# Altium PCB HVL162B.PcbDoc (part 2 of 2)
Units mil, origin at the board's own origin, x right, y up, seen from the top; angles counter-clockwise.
Board outline 4000 x 2700 mil, 2 copper layers (Top Layer, Bottom Layer), stack 62 mil thick; 115 components, 45 nets, 233 pads, 126 vias.
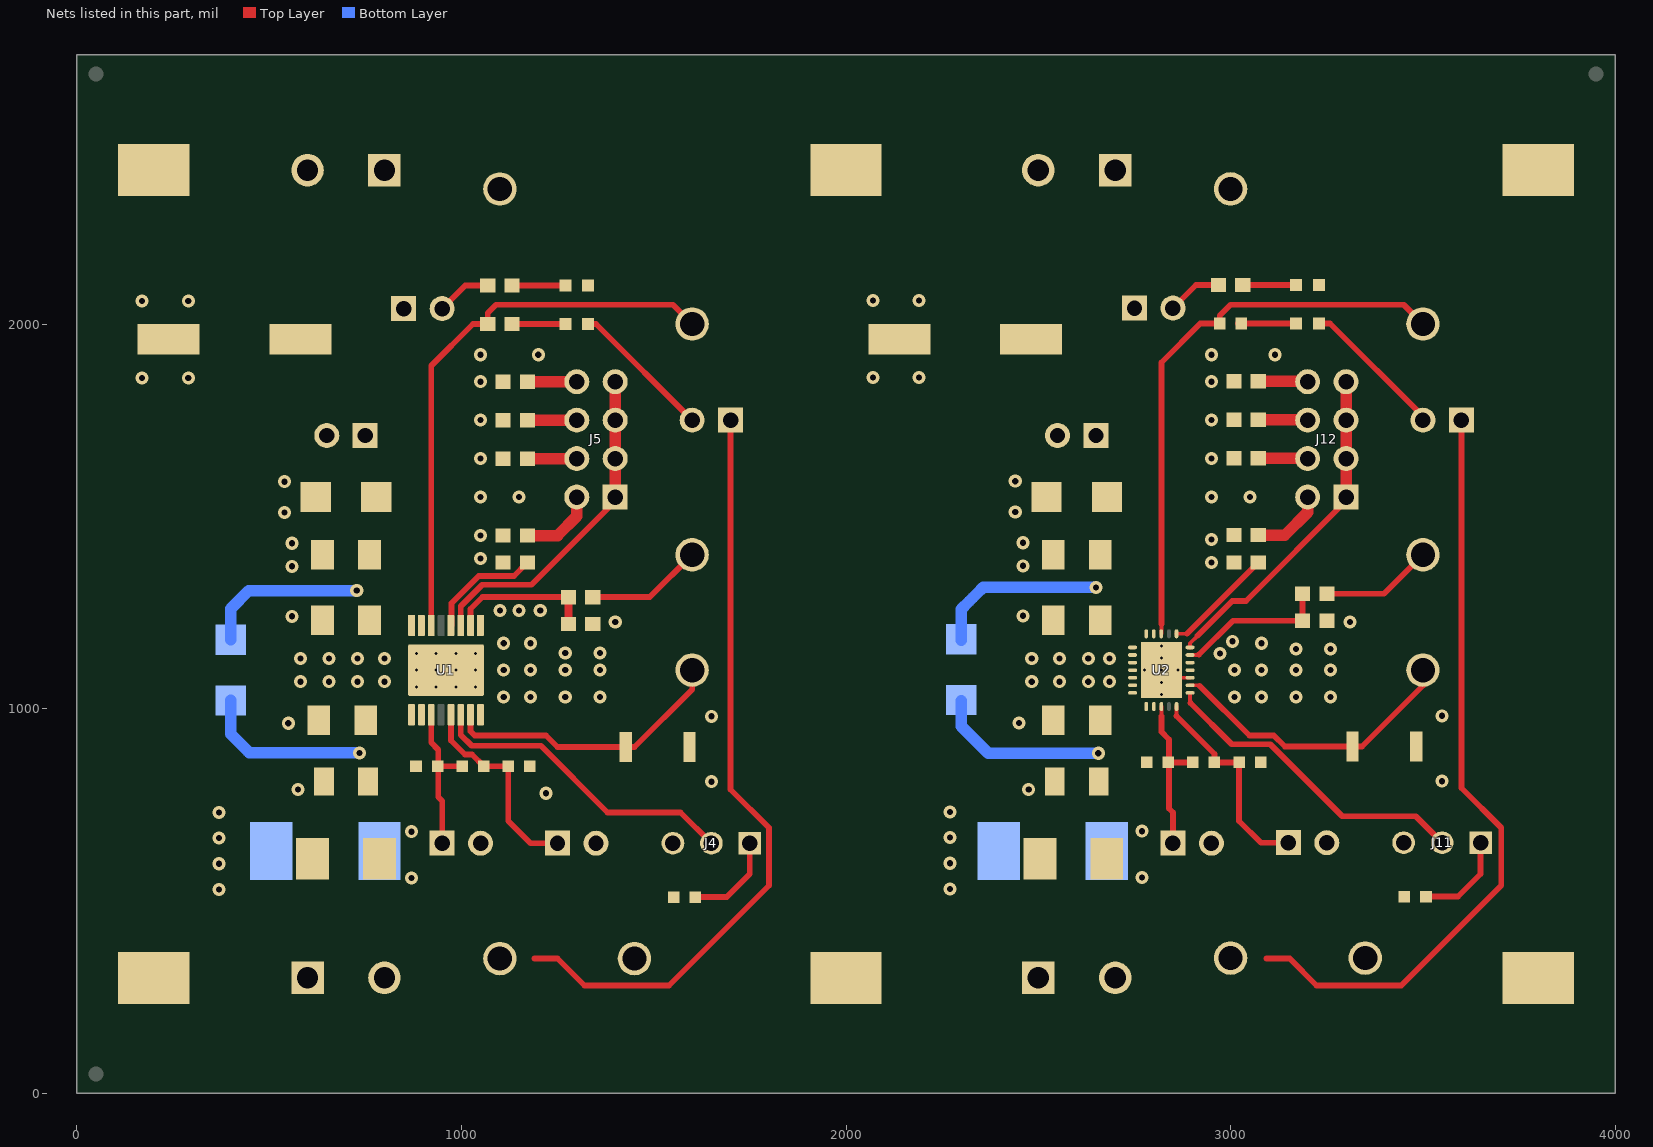
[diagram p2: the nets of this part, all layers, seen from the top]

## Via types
v1: diameter 34, hole 16, Top Layer to Bottom Layer, 107 vias
v2: diameter 19.68, hole 7.87, Top Layer to Bottom Layer, 13 vias
v3: diameter 19.68, hole 7.87, Top Layer to Bottom Layer, tented both sides, 6 vias

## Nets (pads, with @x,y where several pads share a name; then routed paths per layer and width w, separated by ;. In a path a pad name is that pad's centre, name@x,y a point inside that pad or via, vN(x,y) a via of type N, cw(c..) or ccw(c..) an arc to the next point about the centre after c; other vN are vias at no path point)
GND: C1.2 C2.1 C3.2 C4.2 C5.2 C7.2 C8.1 C9.2 C10.2 C11.2 D3.1 D4.1 D5.2 D6.2 D9.1 D10.1 D11.2 D12.2 S1.1 S2.1 T1.1 T2.2 T3.1 T4.2 TP7.1 TP8.1 TP9.1 TP16.1 TP17.1 TP18.1 U1.9 U2.17
  other v1: 370,530 2270,531.3 370,596.67 2270,597.97 370,663.33 2270,664.63 370,730 2270,731.3 575,790 2475,790 1650,810 3550,811.3 550,962 2450,963 1650,980 3550,981.3 2972,1143 3005,1175 560,1240 2460,1241.3 1100,1255 1150,1255 1205,1255 560,1370 2460,1371.3 560,1430 2460,1431.3 540,1510 2440,1511.3 540,1590 2440,1591.3 170,1860 290,1860 2070,1861.3 2190,1861.3 170,2060 290,2060 2070,2061.3 2190,2061.3
NetC5_1: C5.1 J3.2
NetC6_1: C6.1 U1.12 | length 300.6
  Top Layer w15: U1.12@972.8,1216.14 974.15,1216.14 974.15,1274.15 1045,1345 1136.5,1345 C6.1@1171.5,1380
NetC9_1: C9.1 J10.2
NetC12_1: C12.1 U2.20 | length 289.3
  Top Layer w10: U2.20@2859.37,1194.49 2886.32,1194.49
  Top Layer w15: 2886.32,1194.49 C12.1@3071.83,1380
NetD1_1: D1.1 J1.2 | length 374
  Top Layer w15: D1.1@1329.53,2000 1350,2000 J1.2@1600,1750
NetD1_2: D1.2 R1.2 | length 139
  Top Layer w15: R1.2@1131.5,2000 D1.2@1270.47,2000
NetD6_1: D6.1 R5.1 | length 139
  Top Layer w15: R5.1@1131.5,2100 D6.1@1270.47,2100
NetD7_1: D7.1 J8.2 | length 380.4
  Top Layer w15: D7.1@3229.53,2001.3 3258.7,2001.3 3500,1760 J8.2@3500,1750
NetD7_2: D7.2 R13.2 | length 151.8
  Top Layer w15: R13.2@3018.7,2001.3 R13.2@3028,2001.3 D7.2@3170.47,2001.3
NetD12_1: D12.1 R16.1 | length 139
  Top Layer w15: R16.1@3031.5,2101.3 D12.1@3170.47,2101.3
NetJ2_2: J2.2 R5.2 | length 143.4
  Top Layer w15: J2.2@950,2040 1010,2100 R5.2@1068.5,2100
NetJ4_1: J4.1 R7.2 | length 246.9
  Top Layer w15: R7.2@1608,510 1690,510 1750,570 J4.1@1750,650
NetJ4_2: J4.2 U1.6 | length 820.5
  Top Layer w15: U1.6@998.39,983.86 998.39,931.61 1026.75,903.25 1206.75,903.25 1380,730 1570,730 J4.2@1650,650
NetJ5_1: J5.1 J5.3 J5.5 J5.7 U1.11 | length 875
  Top Layer w15: U1.11@998.39,1216.14 998.39,1266.04 1054.47,1322.13 1182.13,1322.13 1400,1540 J5.1@1400,1550
  Top Layer w30: J5.1@1400,1550 J5.3@1400,1650 J5.5@1400,1750 J5.7@1400,1850
NetJ5_2: J5.2 R9.2 | length 199.2
  Top Layer w30: R9.2@1171.5,1450 1250,1450 1300,1500 J5.2@1300,1550
NetJ5_4: J5.4 R10.2 | length 128.5
  Top Layer w30: R10.2@1171.5,1650 J5.4@1300,1650
NetJ5_6: J5.6 R11.2 | length 128.5
  Top Layer w30: R11.2@1171.5,1750 J5.6@1300,1750
NetJ5_8: J5.8 R12.2 | length 128.5
  Top Layer w30: R12.2@1171.5,1850 J5.8@1300,1850
NetJ6_1: J6.1 R2.1 R3.2 U1.3 | length 411.3
  Top Layer w15: U1.3@921.61,983.86 921.61,911.61 940,893.23 940,852 R2.1@938,850 ; J6.1@950,650 950,760 940,770 940,848 R2.1@938,850 ; R3.2@1002,850 R2.1@938,850
NetJ7_1: J7.1 R3.1 R8.2 U1.5 | length 537.7
  Top Layer w15: U1.5@972.8,983.86 972.8,917.2 1009.63,880.37 1027.63,880.37 R3.1@1058,850 R8.2@1122,850 1122,708 1180,650 J7.1@1250,650
NetJ9_2: J9.2 R16.2 | length 143.4
  Top Layer w15: J9.2@2850,2041.3 2910,2101.3 R16.2@2968.5,2101.3
NetJ11_1: J11.1 R19.2 | length 247.6
  Top Layer w15: R19.2@3508,511.3 3591.3,511.3 3650,570 J11.1@3650,651.3
NetJ11_2: J11.2 U2.13 | length 831.7
  Top Layer w10: U2.13@2894.8,1040.94 2894.8,1015.2 2895.75,1014.25
  Top Layer w15: 2895.75,1014.25 3002.87,907.13 3102.87,907.13 3290,720 3481.3,720 J11.2@3550,651.3
NetJ12_1: J12.1 J12.3 J12.5 J12.7 U2.19 | length 879.9
  Top Layer w10: U2.19@2894.8,1159.06 2894.8,1169.8 2913.83,1188.83 2913.83,1189.65
  Top Layer w15: 2913.83,1189.65 3004.18,1280 3040,1280 3300.33,1540.33 J12.1@3300.33,1550
  Top Layer w30: J12.1@3300.33,1550 J12.3@3300.33,1650 J12.5@3300.33,1750 J12.7@3300.33,1850
NetJ12_2: J12.2 R21.2 | length 192.6
  Top Layer w30: R21.2@3071.83,1451.3 3141.3,1451.3 3200.33,1510.33 J12.2@3200.33,1550
NetJ12_4: J12.4 R22.2 | length 127.2
  Top Layer w30: R22.2@3071.83,1651.3 J12.4@3199.03,1651.3
NetJ12_6: J12.6 R23.2 | length 127.2
  Top Layer w30: R23.2@3071.83,1751.3 J12.6@3199.03,1751.3
NetJ12_8: J12.8 R24.2 | length 129
  Top Layer w30: R24.2@3071.83,1851.3 3199.03,1851.3 J12.8@3200.33,1850
NetJ13_1: J13.1 R14.1 R15.2 U2.10 | length 431.9
  Top Layer w10: 2820,980 U2.10@2820,1005.51
  Top Layer w15: 2820,980 2820,940 2840,920 R14.1@2840,860 ; R14.1@2838,860 R14.1@2840,860 ; J13.1@2850,650 2850,730 2840,740 R14.1@2840,860 ; R15.2@2902,860 R14.1@2840,860
NetJ14_1: J14.1 R15.1 R20.2 U2.12 | length 553.9
  Top Layer w10: 2859.37,980.63 U2.12@2859.37,1005.51
  Top Layer w15: 2859.37,980.63 2958,882 R15.1@2958,860 R20.2@3022,860 3022,708 3078.7,651.3 J14.1@3150,651.3
NetR1_1: R1.1 TP1.1 U1.14 | length 1456.9
  Top Layer w15: U1.14@921.61,1216.14 921.61,1891.61 1030,2000 R1.1@1068.5,2000 1068.5,2028.5 1090,2050 1550,2050 TP1.1@1600,2000
NetR4_1: R4.1 TP5.1 | length 304.1
  Top Layer w15: R4.1@1341.5,1290 1490,1290 TP5.1@1600,1400
NetR4_2: R4.2 R6.2 U1.10 | length 380.7
  Top Layer w15: U1.10@1023.98,1216.14 1023.98,1259.28 1055.07,1290.37 1231.37,1290.37 1231.74,1290 R4.2@1278.5,1290
  Top Layer w20: R6.2@1278.5,1220 R4.2@1278.5,1290
NetR13_1: R13.1 TP10.1 U2.22 | length 1480.5
  Top Layer w10: U2.22@2820,1194.49 2820,1220
  Top Layer w15: 2820,1220 2820,1900 2921.3,2001.3 R13.1@2972,2001.3 2972,2022 3000,2050 3450,2050 TP10.1@3500,2000
NetR17_1: R17.1 TP14.1 | length 291.8
  Top Layer w15: R17.1@3250.2,1298.7 3398.7,1298.7 TP14.1@3500,1400
NetR17_2: R17.2 R18.2 U2.18 | length 400.2
  Top Layer w10: U2.18@2894.8,1139.37 2919.37,1139.37
  Top Layer w15: 2918,1140.74 3005.96,1228.7 R18.2@3187.2,1228.7 R17.2@3187.2,1298.7
NetS1_2: S1.2 TP4.1 U1.7 | length 748
  Top Layer w15: U1.7@1023.98,983.86 1023.98,941.02 1035,930 1220,930 1250,900 S1.2@1427.32,900 1450,900 1600,1050 TP4.1@1600,1100
NetS2_2: S2.2 TP13.1 U2.14 | length 776.5
  Top Layer w10: U2.14@2894.8,1060.63 2919.37,1060.63
  Top Layer w15: 2919.37,1059.63 3049,930 3112.35,930 3141.05,901.3 S2.2@3317.32,901.3 3341.3,901.3 3500,1060 TP13.1@3500,1100
RTN1: C6.2 J4.3 J6.2 J7.2 R6.1 R7.1 R8.1 R9.1 R10.1 R11.1 R12.1 TP6.1 U1.8 U1.17@960,1100
  other v1: 1220,780 1110,1030 1180,1030 1270,1030 1360,1030 582,1070 656,1070 730,1070 800,1070 1110,1100 1180,1100 1270,1100 1360,1100 582,1130 656,1130 730,1130 800,1130 1270,1145 1360,1145 1110,1170 1180,1170 1400,1225 1050,1390 1050,1450 1050,1550 1150,1550 1050,1650 1050,1750 1050,1850 1050,1920 1200,1920
  other v2: 934.41,1056.69 985.59,1056.69 934.41,1100 985.59,1100 934.41,1143.31 985.59,1143.31
  other v3: 883.23,1056.69 1036.77,1056.69 883.23,1100 1036.77,1100 883.23,1143.31 1036.77,1143.31
RTN2: C12.2 J11.3 J13.2 J14.2 R18.1 R19.1 R20.1 R21.1 R22.1 R23.1 R24.1 TP15.1 U2.1 U2.2 U2.3 U2.4 U2.5 U2.6 U2.7 U2.15 U2.16 U2.25 | length 55.1
  Top Layer w10: U2.25@2839.69,1080.31 U2.15@2894.8,1080.31
  other v1: 3010,1030 3080,1030 3170,1030 3260,1030 2483,1070 2555,1070 2630,1070 2685,1070 3010,1100 3080,1100 3170,1100 3260,1100 2483,1130 2555,1130 2630,1130 2685,1130 3170,1155 3260,1155 3080,1170 3310,1225 2950.33,1380 2950.33,1440 2950.33,1550 3050.33,1550 2950.33,1650 2950.33,1750 2950.33,1850 2950.33,1920 3115,1920
  other v2: 2820,1037.01 2820,1068.5 2776.69,1100 2820,1100 2863.31,1100 2820,1131.5 2820,1162.99
VIN1: C1.1 C2.2 D2.2 D3.2 D4.2 J1.1 R2.2 T1.2 TP2.1 U1.1 U1.2 | length 2440.7
  Top Layer w15: 1190,350 1250,350 1320,280 1540,280 1800,540 1800,690 1700,790 J1.1@1700,1750
  Bottom Layer w30: D2.2@400,1021.26 400,934 445,889 449,885 v1(735,885)
  other v1: 870,560 870,680
VIN2: C7.1 C8.2 D8.2 D9.2 D10.2 J8.1 R14.2 T3.2 TP11.1 U2.8 U2.9 | length 2450.6
  Top Layer w15: 3093.63,350 3153.63,350 3223.63,280 3443.63,280 3703.63,540 3703.63,690 3600,793.63 J8.1@3600,1750
  Bottom Layer w30: D8.2@2300,1020 2300,954 2370,884 v1(2656,884)
  other v1: 2770,561.3 2770,681.3
VOUT1: C3.1 C4.1 D2.1 D5.1 J2.1 J3.1 T2.1 TP3.1 U1.15 U1.16 | length 428.7
  Bottom Layer w30: D2.1@400,1178.74 400,1260 447,1307 v1(728,1307)
VOUT2: C10.1 C11.1 D8.1 D11.1 J9.1 J10.1 T4.1 TP12.1 U2.23 U2.24 | length 454.6
  Bottom Layer w30: D8.1@2300,1177.48 2300,1258.74 2320,1278.74 2330,1288.74 2352.26,1311 2356.26,1315 v1(2650,1315)
pads on no net: FID1.1 FID2.1 FID3.1 H1.0 H2.0 H3.0 H4.0 SH-J1.0 SH-J2.0 SH-J3.0 SH-J4.0 SH-J5.0 SH-J6.0 SH-J7.0 SH-J8.0 SH-J9.0 SH-J10.0 SH-J11.0 SH-J12.0 SH-J13.0 SH-J14.0 U1.4 U1.13 U1.17@960,1100 U2.11 U2.21

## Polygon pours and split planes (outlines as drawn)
GND on Bottom Layer "BOTTOM_LAYER_GND_P018" (solid, remove dead copper, pour order 18): 50,2650 3945,2650 3945,50 50,50
RTN1 on Bottom Layer "BOTTOM_LAYER_RTN1_P003" (solid, remove dead copper, pour order 3): 1200,300 1600,300 1600,1950 1030,1950 1010,1930 1010,1360 1050,1320 1270,1320 1270,1184 562,1184 562,1000 900,1000 900,500 1200,500
RTN2 on Bottom Layer "BOTTOM_LAYER_RTN2_P001" (solid, remove dead copper, pour order 1): 2461,1175 2495,1175 2875,1175 2880,1170 2880,1150 2880,1106 2886,1100 2965,1100 2986,1100 3091,1205 3150.72,1205 3158.72,1213 3161,1215.28 3161,1280 3161,1297 3151,1307 3150,1308 3102,1308 2944,1308 2931,1321 2928,1324 2928,1356 2928,1948 2930,1950 3030,1950 3481.17,1950 3500,1931.17 3500,1900.21 3500,313 3490,303 3488,301 3438,301 3113,301 3100,314 3100,384 3100,488 3087,501 3086,502 3028,502 2814,502 2800,516 2800,744 2800,987 2774,1013 2766,1021 2679,1021 2500,1021 2461,1021
GND on Top Layer "TOP_LAYER_GND_P016" (solid, remove dead copper, pour order 16): 50,50 4000,50 4000,2650 50,2650
RTN1 on Top Layer "TOP_LAYER_RTN1_P000" (solid, remove dead copper, pour order 0): 1200,300 1600,300 1600,1950 900,1950 900,1176 562,1176 562,1024 900,1024 900,500 1200,500
RTN2 on Top Layer "TOP_LAYER_RTN2_P002" (solid, remove dead copper, pour order 2): 3100,300 3500,300 3500,1950 2800,1950 2800,1175 2460,1175 2460,1021 2800,1021 2800,500 3100,500

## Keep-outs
Keep-Out Layer:
  the board outline again, w10
  text ".Layer_Name" at 577,-858.49 h60

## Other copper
Top Layer:
  rectangle net NetC9_1: 2400,1660 2580,2060
  rectangle net NetC5_1: 500,1660 680,2060
  rectangle net RTN1: 1050,960 1090,1020
  region net VOUT1: 900,1250 900,1243 903,1240 903,1193 897,1193
  region net GND: 1044.65,1220 1044.65,1254.65 1065,1275 1225,1275 1235,1265 1235,1240 1225,1230 1135,1230 1093.98,1230 1054.49,1190.51 1044.65,1206.23
  region net VOUT2: 2600,1200 2600,2412 2638,2450 3070,2450 3100,2420 3100,2220 3080,2200 2940,2200 2820,2200 2800,2180 2800,1220 2800,1185 2615,1185
  region net VIN1: 700,260 700,1000 720,1020 890,1020 900,1010 900,970 900,520 920,500 1180,500 1200,480 1200,260 1180,240 960,240 720,240
  region net VOUT1: 700,1200 700,2450 720,2470 950,2470 1180,2470 1200,2450 1200,2220 1180,2200 1040,2200 920,2200 900,2180 900,1190 890,1180 720,1180
  region net GND: 2924,1125 2994,1195 3029,1195 3034,1190 3034,1168 2980,1114 2885,1115 2885,1125
  region net RTN2: 2766.98,1171 2767,1034 2775,1026 2776,1027 2873,1027 2874,1028 2874,1071 2878,1075 2947.79,1075 2977.79,1045 3007,1045 3014,1052 3014,1085 2993,1106 2875,1106 2873,1108 2873,1171
  region net VIN2: 2600,260 2600,1000 2617,1017 2800,1017 2804,1013 2804,516 2820,500 3080,500 3100,480 3100,260 3080,240 2860,240 2620,240
  pour cut-out: 3944.53,85.71 3910,51.19 3910,45 3960,45 3944.53,60.47
  text ".Layer_Name" at 577,-858.49 h60
Bottom Layer:
  region net VIN1: 700,710 720,730 880,730 900,710 900,260 880,240 730,240 700,260
  region net VIN2: 2600,710 2620,730 2780,730 2800,710 2800,260 2780,240 2630,240 2600,260
  pour cut-out: 3960,101.19 3903.81,45 3960,45
  pour cut-out: 3891.91,2645 3948.09,2588.81 3948.09,2645
  pour cut-out: 55,2588.81 111.19,2645 55,2645
  pour cut-out: 111.19,55 55,111.19 55,55
  text ".Layer_Name" at 577,-858.49 h60

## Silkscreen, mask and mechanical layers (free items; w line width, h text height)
Top Overlay:
  lines w10: 550,930 550,880 705,880 ; 550,990 550,1210 ; 550,1270 550,1310 700,1310 ; 755,1315 1020,1315 1020,1495 1215,1495 1215,1340 1400,1340 1400,1255 ; 765,880 835,880 835,810 1225,810 1225,1175 1400,1175 ; 1400,1180 1400,1175 ; 1400,1195 1400,1175 ; 2000,497 2000,2215 ; 2450,935 2450,880 2625,880 ; 2450,995 2450,1215 ; 2450,1270 2450,1315 2620,1315 ; 2680,1315 2915,1315 2915,1490 2915,1495 2950,1495 3120,1495 3120,1345 3300,1345 3300,1255 ; 2685,880 2730,880 2730,815 3130,815 3130,1185 3300,1185 ; 3300,1190 3300,1185 ; 3300,1195 3300,1185
  text "-" at 530,2600 h100
  text "+" at 830,2600 h100
  text "-" at 2430,2600 h100
  text "+" at 2730,2600 h100
  text "TPS26600-02EVM" at 1040,2545 h60
  text "+" at 645,2095 h100
  text "+" at 2550,2065 h100
  text "." at 2705,1145 h200
  text "." at 859,927 h200
  text "'.PRJ_Number''.PCB_Rev'" at 260,850 h60 r90
  text "3" at 1534.75,720 h72.83
  text "2" at 1634.46,720 h72.83
  text "1" at 1741.4,720 h72.83
  text "3" at 3434.75,720 h72.83
  text "2" at 3534.46,720 h72.83
  text "1" at 3641.4,720 h72.83
  text "RTN2" at 3281,209 h40
  text "VIN2" at 2947,203 h40
  text "-" at 550,50 h100
  text "-" at 2450,50 h100
  text "+" at 810,40 h100
  text "+" at 2710,40 h100
  text ".Layer_Name" at 577,-858.49 h60
Bottom Overlay:
  text ".Layer_Name" at 577,-858.49 h60
Top Paste:
  text ".Layer_Name" at 577,-858.49 h60
Bottom Paste:
  text ".Layer_Name" at 577,-858.49 h60
Top Solder:
  text ".Layer_Name" at 577,-858.49 h60
  text ".Layer_Name" at 577,-858.49 h60
Bottom Solder:
  text ".Layer_Name" at 577,-858.49 h60
Drill Guide:
  text ".Layer_Name" at 577,-858.49 h60
M1 Board Outline:
  the board outline again, w10
  text ".Layer_Name" at 577,-858.49 h60
M2 Board Dimensions:
  rectangle: 125,-400 500,-275
  rectangle: 0,-275 125,-150
  lines w7: 0,-275 1000,-275 ; 125,-400 125,-150 ; 250,-400 250,-150 ; 500,-400 500,-150 ; 750,-400 750,-150 ; 0,-400 0,-150 1000,-150 1000,-400 0,-400
  text ".Layer_Name" at 577,-858.49 h60
M3 3D STEP Top:
  text ".Layer_Name" at 577,-858.49 h60
M4 3D STEP Bottom:
  text ".Layer_Name" at 577,-858.49 h60
M5 Assembly Top:
  circle w10: c745,1710 r11.18
  circle w10: c1228.82,650 r11.18
  circle w10: c928.82,665 r11.18
  circle w10: c1708.82,1755 r11.18
  circle w10: c818.82,2060 r11.18
  circle w10: c2738.82,2050 r11.18
  circle w10: c3603.82,1745 r11.18
  circle w10: c2673.82,1720 r11.18
  circle w10: c2823.82,670 r11.18
  circle w10: c3118.82,675 r11.18
  lines w10: -292,-930.17 6308,-930.17 ; -292,-726.83 6310,-726.83 ; -292,-523.5 -292,-1133.5 3713,-1133.5 6310,-1133.5 6310,-523.5 -291.5,-523.5 -291.5,-1133.5 1284,-1133.5 ; 2173,-1133.5 2173,-523.5 ; 3440,-726.83 3440,-523.5 ; 4280,-726.83 4280,-523.5 ; 4902,-1140 4902,-937.17
  text "+" at 2445,1945 h40
  text "+" at 555,1935 h40
  text "COMPONENTS MARKED 'DNP' SHOULD NOT BE POPULATED." at 1153.5,-318.5 h60
  text "ASSEMBLY VARIANT:" at 1153,-434 h60
  text ".VariantName" at 2189,-434 h60
  text "PCB VIEWED FROM TOP SIDE" at -228.5,-655.67 h60
  text "BOARD #:" at 2248,-655.67 h60
  text ".PRJ_Number" at 2793.5,-655.67 h60
  text "REV:" at 3638,-655.67 h60
  text ".PCB_Rev" at 3929.5,-655.67 h60
  text "SVN REV:" at 4476,-655.67 h60
  text ".VersionControl_RevNumber" at 4982,-655.67 h60
  text "TID #:" at 2248,-859 h60
  text ".TID" at 2793.5,-859 h60
  text "PLOT NAME =" at -228.5,-1064.34 h60
  text ".plot_File_Name" at 577,-1064.34 h60
  text "GENERATED    :" at 2250,-1064.34 h60
  text ".Print_Date" at 3119.5,-1064.34 h60
  text ".Print_Time" at 3848.5,-1064.34 h60
  text "TEXAS INSTRUMENTS" at 5113,-1064.34 h60
M6 Assembly Bottom:
  lines w10: -292.5,-727.33 6309.5,-727.33 ; -290.5,-930.67 6309.5,-930.67 ; 1115.5,-1140.5 1115.5,-937.67 ; 1737.5,-727.33 1737.5,-524 ; 2577.5,-727.33 2577.5,-524 ; 3844.5,-1134 3844.5,-524 ; 4733.5,-1134 6309,-1134 6309,-524 -292.5,-524 -292.5,-1134 2304.5,-1134 6309.5,-1134 6309.5,-524
  text "COMPONENTS MARKED 'DNP' SHOULD NOT BE POPULATED." at 6102,-318 h60
  text ".VariantName" at 5058,-434 h60
  text "ASSEMBLY VARIANT:" at 6097,-434 h60
  text ".VersionControl_RevNumber" at 1035.5,-656.17 h60
  text "SVN REV:" at 1541.5,-656.17 h60
  text ".PCB_Rev" at 2088,-656.17 h60
  text "REV:" at 2379.5,-656.17 h60
  text ".PRJ_Number" at 3224,-656.17 h60
  text "BOARD #:" at 3769.5,-656.17 h60
  text "PCB VIEWED FROM BOTTOM SIDE" at 6246,-656.17 h60
  text ".TID" at 3224,-859.5 h60
  text "TID #:" at 3769.5,-859.5 h60
  text "TEXAS INSTRUMENTS" at 904.5,-1064.84 h60
  text ".Print_Time" at 2169,-1064.84 h60
  text ".Print_Date" at 2898,-1064.84 h60
  text "GENERATED    :" at 3767.5,-1064.84 h60
  text ".plot_File_Name" at 5440.5,-1064.84 h60
  text "PLOT NAME =" at 6246,-1064.84 h60
M9 Title Sheet:
  drawing of 57 lines, arcs and shapes, not listed
  text "1" at 739.84,8036.5 h70
  text "2" at 3235.5,8036.5 h70
  text "3" at 5724.84,8036.5 h70
  text "4" at 8231.51,8036.5 h70
  text "5" at 10730.5,8036.5 h70
  text "6" at 13235.5,8036.5 h70
  text "A" at -416.5,6893.5 h70
  text "A" at 14383.5,6893.5 h70
  text "B" at -416.5,4513.5 h70
  text "B" at 14383.5,4513.5 h70
  text "C" at -416.5,2138.5 h70
  text "C" at 14383.5,2138.5 h70
  text "PROJECT TITLE:" at 11343.5,277.5 h45
  text ".PRJ_Title" at 11393.5,144.17 h70
  text "DESIGNED FOR:" at 11343.5,-23.5 h45
  text ".PRJ_Customer" at 11393.5,-163.5 h70
  text "D" at -416.5,-231.5 h70
  text "D" at 14383.5,-231.5 h70
  text "FILE NAME:" at 11343.5,-323.5 h45
  text ".PCB_File_Name_No_Path" at 11393.5,-443.5 h70
  text "Texas Instruments (TI) and/or its licensors do not warrant the accuracy or completeness of this specification" at 6374,-605.34 h45
  text "ENGINEER:" at 11343.5,-613.5 h45
  text "LAYOUT BY:" at 12848.5,-613.5 h45
  text "or any information contained therein. TI and/or its licensors do not warrant that this design will meet" at 6329.01,-718 h45
  text ".PRJ_Engineer" at 11393.5,-768.49 h70
  text ".PCB_Layout" at 12899,-768.49 h70
  text "the specifications, will be suitable for your application or fit for any particular purpose, or will operate in" at 6329.01,-830.67 h45
  text ".Layer_Name" at 577,-858.49 h60
  text "ALTIUM DESIGNER VERSION:" at 12848.5,-923.5 h45
  text "an implementation. TI and/or its licensors do not warrant that the design is production worthy. You should" at 6329.01,-943.33 h45
  text "completely validate and test your design implementation to confirm the system functionality for your application." at 6374,-1056 h45
  text ".print_Scale" at 11393.5,-1056.83 h70
  text ".Application_BuildNumber" at 12899,-1056.83 h70
  text "1" at 739.84,-1263.5 h70
  text "2" at 3235.5,-1263.5 h70
  text "3" at 5724.84,-1263.5 h70
  text "4" at 8231.51,-1263.5 h70
  text "5" at 10730.5,-1263.5 h70
  text "6" at 13235.5,-1263.5 h70
M10 Fab Notes:
  drawing of 173 lines, arcs and shapes, not listed
  text "Copper Thickness is 2oz." at 11290,6815 h60
  text "Vias are not tented." at 11295,6715 h60
  text "DESIGN INFORMATION" at 12378.02,6201 h60
  text "MIN. TRACK WIDTH:" at 11733.46,6021 h60
  text "MIL" at 12984.46,6021 h60
  text "10" at 12780,6010 h60
  text "MIN. CLEARANCE:" at 11733.46,5889 h60
  text "MIL" at 12989.46,5886 h60
  text "7.874" at 12695,5885 h60
  text "MIN. VIA PAD SIZE:" at 11733.46,5757 h60
  text "19.685" at 12645,5755 h60
  text "MIL" at 12990,5755 h60
  text "0.15mm (5.9MIL)" at 12428.46,5615.29 h60
  text "MINIMUM ANNULAR RING" at 11404.23,5611 h60
  text "EXTERNAL" at 13136.46,5611 h60
  text "PER" at 11604.23,5493 h60
  text "IPC-D-275 CLASS 2 LEVEL C" at 11824.23,5493 h60
  text "MIL, HOLES" at 13312.46,5380.71 h60
  text "+/-" at 12920,5380 h60
  text "+/-" at 13774,5380 h60
  text "REGISTRATION TOLERANCES:" at 11404.23,5375 h60
  text "METAL" at 12604,5375 h60
  text "5" at 13180.2,5375 h60
  text "3" at 14013.2,5375 h60
  text "MIL" at 14129.46,5375 h60
  text "+/-" at 13774,5262 h60
  text "HOLE SIZE TOLERANCE (UNLESS OTHERWISE SPECIFIED):" at 11404.23,5257 h60
  text "3" at 14013.2,5257 h60
  text "MIL" at 14129.46,5257 h60
  text "MATERIAL:" at 11329.46,5047.54 h60
  text "FR-4 High Tg" at 12315.9,4907.21 h60
  text "FR-408" at 11750.46,4898.64 h60
  text "OTHER" at 13238.46,4898.64 h60
  text "X" at 12161,4895 h60
  text "62 MIL (1.6mm) +/-10%" at 12070.56,4735.92 h60
  text "THICKNESS:" at 11404.23,4731.64 h60
  text "X" at 11942.4,4731.64 h60
  text "OTHER" at 13355.46,4731.64 h60
  text "TOLERANCE:" at 11404.23,4573.64 h60
  text "X" at 12243.53,4573.64 h60
  text "ANSI IPC-6012 TYPE 3 CLASS 2" at 12430.48,4573.64 h60
  text "OTHER +/-" at 12430.46,4417.64 h60
  text "BOW & TWIST:" at 11404.23,4260.64 h60
  text "X" at 12243.53,4260.64 h60
  text "ANSI IPC-6012 TYPE 3 CLASS 2" at 12430.48,4260.64 h60
  text "OTHER +/-" at 12430.46,4102.13 h60
  text "DRILLING:" at 11329.46,3963.64 h60
  text "REFERENCE:" at 11404.23,3846.64 h60
  text "X" at 12052.46,3846.64 h60
  text "AS SHOWN" at 12239.46,3846.64 h60
  text "X" at 12953.46,3846.64 h60
  text "NC_DRILL FILES" at 13090.46,3846.64 h60
  text "PTH COPPER THICKNESS:" at 11404.23,3688.64 h60
  text "X" at 12534.46,3688.64 h60
  text "20-30 um" at 12671.46,3688.64 h60
  text "OTHER" at 13388.46,3688.64 h60
  text "BOARD FINISH:" at 11329.46,3529.64 h60
  text "SILKSCREEN:" at 11484.68,3411.64 h60
  text "X" at 12433.46,3411.64 h60
  text "TOP" at 12559.46,3411.64 h60
  text "X" at 12943.46,3411.64 h60
  text "BOTTOM" at 13070.46,3411.64 h60
  text "SILKSCREEN COLOR:" at 11484.68,3244.64 h60
  text "X" at 12432.42,3244.64 h60
  text "WHITE" at 12559.46,3244.64 h60
  text "OTHER" at 13070.46,3244.64 h60
  text "X" at 12563.42,3085.44 h60
  text "GREEN" at 12690.46,3085.44 h60
  text "OTHER" at 13308.46,3085.44 h60
  text "SOLDER RESIST COLOR:" at 11484.68,3074.64 h60
  text "X" at 12563.42,2915.44 h60
  text "MATTE" at 12690.46,2915.44 h60
  text "SEMI-GLOSS" at 13308,2914.8 h60
  text "IMMERSION GOLD (ENIG)" at 12390.46,2726.92 h60
  text "ENEPIG" at 13728,2723.64 h60
  text "SURFACE FINISH:" at 11329.46,2722.64 h60
  text "X" at 12203.51,2722.64 h60
  text "IMM. TIN/SILVER OR EQUIV" at 11659,2565.64 h60
  text "OTHER" at 13090.46,2565.64 h60
  text "ARRAY/PANEL:" at 11329.46,2386.64 h60
  text "CUT AND TRIM PER M1 BOARD OUTLINE" at 12390.46,2382.35 h60
  text "N.C. ROUTE" at 12390.46,2230.64 h60
  text "X" at 13069.46,2230.64 h60
  text "V. SCORE" at 13256.46,2230.64 h60
  text "CERTIFICATION:" at 11329.46,2093.64 h60
  text "MATERIALS AND WORKMANSHIP FOR ALL PCBS" at 12054.46,2093.64 h60
  text "TO MEET OR EXCEED THE REQUIREMENTS OF:" at 12054.46,1995.64 h60
  text "X" at 11680.96,1859.13 h60
  text "ANSI IPC-A-600F CLASS ->" at 11819.96,1859.13 h60
  text "X" at 13459.02,1859.13 h60
  text "2" at 13577.96,1859.14 h60
  text "1" at 13262.96,1857.64 h60
  text "3" at 13931.96,1857.64 h60
  text "X" at 12495.02,1699.64 h60
  text "RoHS" at 12631.96,1699.64 h60
  text "OTHER" at 13276.36,1699.64 h60
  text "PER ORDER" at 13673.42,1699.64 h60
  text "ALL BOARDS MUST MEET OR EXCEED UL94-V0 REQUIREMENTS." at 11357,1534 h60
  text "PCB MUST BEAR THE UL94V-0 UL REGISTERED MATERIAL ID NUMBER" at 11357,1414 h60
  text "ADDITIONAL REQUIREMENTS:" at 11329.46,1240.64 h60
  text "MICROSECTION:" at 11404.23,1125.64 h60
  text "YES" at 12309.96,1125.64 h60
  text "REQUIRED" at 13171.46,969.49 h60
  text "BARE BOARD ELEC. TEST:" at 11404.23,966.64 h60
  text "NONE" at 12709.96,966.64 h60
  text "X" at 13044.46,966.64 h60
  text "PER ORDER" at 13763.46,966.64 h60
  text ".Layer_Name" at 577,-858.49 h60
M11 Gerber Information:
  lines w10: -292,-930.17 6308,-930.17 ; -292,-726.83 6310,-726.83 ; -292,-523.5 -292,-1133.5 3713,-1133.5 6310,-1133.5 6310,-523.5 -291.5,-523.5 -291.5,-1133.5 1284,-1133.5 ; 2173,-1133.5 2173,-523.5 ; 3440,-726.83 3440,-523.5 ; 4280,-726.83 4280,-523.5 ; 4902,-1140 4902,-937.17
  text "ALL ARTWORK VIEWED FROM TOP SIDE" at -228.5,-655.67 h60
  text "BOARD #:" at 2248,-655.67 h60
  text ".PRJ_Number" at 2793.5,-655.67 h60
  text "REV:" at 3638,-655.67 h60
  text ".PCB_Rev" at 3929.5,-655.67 h60
  text "SVN REV:" at 4476,-655.67 h60
  text ".VersionControl_RevNumber" at 4982,-655.67 h60
  text "LAYER NAME =" at -228.5,-858.49 h60
  text "TID #:" at 2248,-859 h60
  text ".TID" at 2793.5,-859 h60
  text "PLOT NAME =" at -228.5,-1064.34 h60
  text ".plot_File_Name" at 577,-1064.34 h60
  text "GENERATED    :" at 2250,-1064.34 h60
  text ".Print_Date" at 3119.5,-1064.34 h60
  text ".Print_Time" at 3848.5,-1064.34 h60
  text "TEXAS INSTRUMENTS" at 5113,-1064.34 h60
M12 Stackup:
  drawing of 191 lines, arcs and shapes, not listed
  text "Layer" at 9732.5,7802.5 h60
  text "Name" at 10142.41,7802.5 h60
  text "Material" at 11072.16,7802.5 h60
  text "Thickness" at 11931.92,7802.5 h60
  text "Constant" at 12581.76,7802.5 h60
  text "Board Layer Stack" at 13151.62,7802.5 h60
  text "1" at 9732.5,7682.5 h60
  text "Top Overlay" at 10142.41,7682.5 h60
  text "2" at 9732.5,7562.5 h60
  text "Top Solder" at 10142.41,7562.5 h60
  text "Solder Resist" at 11072.16,7562.5 h60
  text "0.40mil" at 11931.92,7562.5 h60
  text "3.5" at 12581.76,7562.5 h60
  text "3" at 9732.5,7442.5 h60
  text "Top Layer" at 10142.41,7442.5 h60
  text "Copper" at 11072.16,7442.5 h60
  text "1.40mil" at 11931.92,7442.5 h60
  text "4" at 9732.5,7322.5 h60
  text "Dielectric1" at 10142.41,7322.5 h60
  text "FR-4 High Tg" at 11072.16,7322.5 h60
  text "59.20mil" at 11931.92,7322.5 h60
  text "4.8" at 12581.76,7322.5 h60
  text "5" at 9732.5,7202.5 h60
  text "Bottom Layer" at 10142.41,7202.5 h60
  text "Copper" at 11072.16,7202.5 h60
  text "1.40mil" at 11931.92,7202.5 h60
  text "6" at 9732.5,7082.5 h60
  text "Bottom Solder" at 10142.41,7082.5 h60
  text "Solder Resist" at 11072.16,7082.5 h60
  text "0.40mil" at 11931.92,7082.5 h60
  text "3.5" at 12581.76,7082.5 h60
  text "7" at 9732.5,6962.5 h60
  text "Bottom Overlay" at 10142.41,6962.5 h60
  text ".Layer_Name" at 577,-858.49 h60
M13 Component Bodies Top:
  text ".Layer_Name" at 577,-858.49 h60
M14 Component Bodies Bottom:
  text ".Layer_Name" at 577,-858.49 h60
M15 Courtyards Top:
  text ".Layer_Name" at 577,-858.49 h60
M16 Courtyards Bottom:
  text ".Layer_Name" at 577,-858.49 h60
Drill Drawing:
  lines w10: 3902.29,4912.5 3935.62,4929.17 3968.96,4912.5 3952.29,4945.83 3968.96,4979.17 3935.62,4962.5 3902.29,4979.17 3918.96,4945.83 3902.29,4912.5 ; 3902.29,5129.17 3968.96,5129.17 3935.62,5062.5 3902.29,5129.17 ; 3902.29,5229.17 3918.96,5229.17 3918.96,5212.5 3952.29,5212.5 3952.29,5229.17 3968.96,5229.17 3968.96,5262.5 3952.29,5262.5 3952.29,5279.17 3918.96,5279.17 3918.96,5262.5 3902.29,5262.5 3902.29,5229.17 ; 3902.29,5362.5 3968.96,5362.5 3968.96,5429.17 3902.29,5429.17 3902.29,5362.5 ; 3902.29,5529.17 3918.96,5529.17 3935.62,5512.5 3952.29,5529.17 3968.96,5529.17 3952.29,5545.83 3968.96,5562.5 3952.29,5562.5 3935.62,5579.17 3918.96,5562.5 3902.29,5562.5 3918.96,5545.83 3902.29,5529.17
  lines w15: 3842.5,4867.5 10962.57,4867.5 ; 3842.5,5617.5 10962.57,5617.5 ; 4393.38,4717.5 4393.38,5767.5 ; 4983.22,4717.5 4983.22,5767.5 ; 6192.86,4717.5 6192.86,5767.5 ; 6698.74,4717.5 6698.74,5767.5 ; 7432.54,4717.5 7432.54,5767.5 ; 8932.09,4717.5 8932.09,5767.5 ; 9521.94,4717.5 9521.94,5767.5 ; 10267.74,4717.5 10267.74,5767.5 ; 3842.5,4717.5 10962.57,4717.5 10962.57,5767.5 3842.5,5767.5 3842.5,4717.5
  text "Symbol" at 3932.5,5662.5 h72
  text "Count" at 4438.38,5662.5 h72
  text "Hole Size" at 5028.22,5662.5 h72
  text "Plated" at 6237.86,5662.5 h72
  text "Hole Type" at 6743.74,5662.5 h72
  text "Drill Layer Pair" at 7477.54,5662.5 h72
  text "Via/Pad" at 8977.09,5662.5 h72
  text "Pad Shape" at 9566.94,5662.5 h72
  text "Template" at 10312.74,5662.5 h72
  text "8" at 4438.38,5512.5 h60
  text "55.12mil (1.40000mm)" at 5028.22,5512.5 h60
  text "PTH" at 6237.86,5512.5 h60
  text "Round" at 6743.74,5512.5 h60
  text "Top Layer - Bottom Layer" at 7477.54,5512.5 h60
  text "Pad" at 8977.09,5512.5 h60
  text "(Mixed)" at 9566.94,5512.5 h60
  text "(Mixed)" at 10312.74,5512.5 h60
  text "12" at 4438.38,5362.5 h60
  text "63.00mil (1.60020mm)" at 5028.22,5362.5 h60
  text "PTH" at 6237.86,5362.5 h60
  text "Round" at 6743.74,5362.5 h60
  text "Top Layer - Bottom Layer" at 7477.54,5362.5 h60
  text "Pad" at 8977.09,5362.5 h60
  text "Rounded" at 9566.94,5362.5 h60
  text "c221h160" at 10312.74,5362.5 h60
  text "19" at 4438.38,5212.5 h60
  text "7.87mil (0.20000mm)" at 5028.22,5212.5 h60
  text "PTH" at 6237.86,5212.5 h60
  text "Round" at 6743.74,5212.5 h60
  text "Top Layer - Bottom Layer" at 7477.54,5212.5 h60
  text "Via" at 8977.09,5212.5 h60
  text "Rounded" at 9566.94,5212.5 h60
  text "(Mixed)" at 10312.74,5212.5 h60
  text "42" at 4438.38,5062.5 h60
  text "40.00mil (1.01600mm)" at 5028.22,5062.5 h60
  text "PTH" at 6237.86,5062.5 h60
  text "Round" at 6743.74,5062.5 h60
  text "Top Layer - Bottom Layer" at 7477.54,5062.5 h60
  text "Pad" at 8977.09,5062.5 h60
  text "(Mixed)" at 9566.94,5062.5 h60
  text "(Mixed)" at 10312.74,5062.5 h60
  text "107" at 4438.38,4912.5 h60
  text "16.00mil (0.40640mm)" at 5028.22,4912.5 h60
  text "PTH" at 6237.86,4912.5 h60
  text "Round" at 6743.74,4912.5 h60
  text "Top Layer - Bottom Layer" at 7477.54,4912.5 h60
  text "Via" at 8977.09,4912.5 h60
  text "Rounded" at 9566.94,4912.5 h60
  text "v86h41" at 10312.74,4912.5 h60
  text "188 Total" at 4438.38,4762.5 h60
  text "Drill Table" at 4299,4554.6 h60
  text "DRILL TOLERANCE" at 4307,4449.6 h60
  text "FOR PTH +/- 3MIL" at 4313,4363.6 h60
  text "7.874mil drill:+0/-7.874mil" at 4305,4255 h60
  text "16mil drill:+0/-16mil" at 4310,4150 h60
  text ".Layer_Name" at 577,-858.49 h60
M17 Embedded Cavity:
  text ".Layer_Name" at 577,-858.49 h60
M18 Embedded Assembly:
  text ".Layer_Name" at 577,-858.49 h60
M19 Embedded Keepout:
  text ".Layer_Name" at 577,-858.49 h60

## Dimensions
4000,0 to 0,0 on M2 Board Dimensions
0,2700 to 4000,0 on M2 Board Dimensions
0,-400 to 1000,-400 on M2 Board Dimensions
